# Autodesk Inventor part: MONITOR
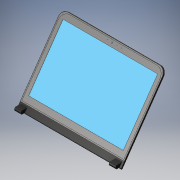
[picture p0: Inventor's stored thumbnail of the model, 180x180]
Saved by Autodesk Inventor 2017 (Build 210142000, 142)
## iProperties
Created: 2017-02
Part Number: MONITOR
Material: Generic
Document SubType Name: Modeling
Designer: Ali
Density: 1 g/cm^3
Appearance: Default
Author: Ali
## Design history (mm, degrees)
sketch "Sketch1"
  geometry: L1 (-145, 250)-(145, 250); L2 (165, 230)-(165, 0); L3 (165, 0)-(-165, 0); L4 (-165, 0)-(-165, 230); A1 r 20 centre (-145, 230) between (-145, 250) and (-165, 230); A2 r 20 centre (145, 230) between (165, 230) and (145, 250); 2 further points
  constraints: 8 end point, 4 point on circle, 4 tangent, 2 centre point, 2 parallel, 2 point on line, 1 equal radius, 1 horizontal, 1 perpendicular
  dimensions: "d2" = 330 distance of L2.end L3.end; "d3" = 250 distance of point (165, 250) L2.end; "d4" = 20 radius of A1 (derived)
extrude "MONITOR" new body sketch "Sketch1" distance "d5" = 5; taper "d6" = 0 deg
sketch "Sketch2"
  geometry: L1 (150, 40)-(-150, 40); L2 (-150, 40)-(-150, 230); L3 (-150, 230)-(150, 230); L4 (150, 230)-(150, 40)
  constraints: 8 end point, 2 parallel, 1 horizontal, 1 perpendicular
  dimensions: "d9" = 300 distance of L2.end L3.end; "d10" = 190 distance of L1.end L2.end
extrude "SCREEN" cut sketch "Sketch2" distance "d11" = 0.5; taper "d12" = 0 deg
sketch "Sketch3"
  geometry: C1 r 2.5 at (0, 240); 1 further point
  constraints: 1 centre point
extrude "CAMERA" join sketch "Sketch3" distance "d14" = 0.25; taper "d15" = 0 deg
sketch "Sketch4"
  geometry: 2 further points
hole "CAMERA" sketch "Sketch4" at (0, 0) diameter "d16" = 1; stored, may be unused: countersink angle "d20" = 90 deg, drill point angle "d22" = 118 deg; dims "d17" = 7.5, "d18" = 3.75, "d19" = 2.5, "d21" = 0.1
sketch "Sketch5"
  geometry: 4 further points
hole "AESTHETICS" sketch "Sketch5" at (15, 240), (30, 240), (-15, 240) diameter "d23" = 1; stored, may be unused: countersink angle "d27" = 90 deg, drill point angle "d29" = 118 deg; dims "d24" = 7.5, "d25" = 3.75, "d26" = 2.5, "d28" = 0.1
sketch "Sketch6"
  geometry: L1 (164.5, 20)-(-164.5, 20); L2 (-164.5, 20)-(-164.5, 229); L3 (-144, 249.5)-(144, 249.5); L4 (164.5, 229)-(164.5, 20); A1 r 20.5 centre (-144, 229) between (-144, 249.5) and (-164.5, 229); A2 r 20.5 centre (144, 229) between (164.5, 229) and (144, 249.5); 2 further points
  constraints: 8 end point, 4 point on circle, 4 point on line, 4 tangent, 2 centre point, 2 parallel, 1 equal radius, 1 horizontal, 1 perpendicular
  dimensions: "d36" = 229.5 distance of L1.end point (-164.5, 249.5); "d37" = 20.5 radius of A1 (derived); "d38" = 329 distance of L1.start L1.end
extrude "SIDE BAND" join sketch "Sketch6" distance "d39" = 0.15; taper "d40" = 0 deg
sketch "Sketch7"
  geometry: L1 (161.5, 23)-(-161.5, 23); L2 (-161.5, 23)-(-161.5, 223); L3 (-138, 246.5)-(138, 246.5); L4 (161.5, 223)-(161.5, 23); A1 r 23.5 centre (-138, 223) between (-138, 246.5) and (-161.5, 223); A2 r 23.5 centre (138, 223) between (161.5, 223) and (138, 246.5); 2 further points
  constraints: 8 end point, 4 point on circle, 4 point on line, 4 tangent, 2 centre point, 2 parallel, 1 equal radius, 1 horizontal, 1 perpendicular
  dimensions: "d47" = 323 distance of point (-161.5, 246.5) point (161.5, 246.5); "d48" = 223.5 distance of L1.end point (-161.5, 246.5); "d49" = 23.5 radius of A1 (derived)
extrude "SIDE BAND 1" cut sketch "Sketch7" distance "d50" = 0.15; taper "d51" = 0 deg
sketch "Sketch8"
  geometry: L1 (0, 0)-(-5, 0); L2 (-5, 0)-(-5, 2.251); L3 (-5, 2.251)-(0, 2.251); L4 (0, 2.251)-(0, 0)
  constraints: 8 end point, 2 parallel, 1 horizontal, 1 perpendicular
extrude "CUT" cut sketch "Sketch8" distance "d52" = 330; taper "d53" = 0 deg
sketch "Sketch9"
  geometry: L1 (0, -227.749)-(5, -227.749); A1 r 2.5 centre (2.5, -227.749) between (0, -227.749) and (5, -227.749)
  constraints: 2 end point, 2 point on circle, 1 centre point
extrude "ROUND BASE" join sketch "Sketch9" distance "d54" = 330; taper "d55" = 0 deg
workplane "Work Plane1"
sketch "Sketch10"
  geometry: L1 (2.296, 5)-(-2.292, 11.553); L2 (2.296, 5)-(10.296, 5); L3 (2.296, 5)-(16.296, 5); L4 (16.296, 5)-(7.102, 18.131); A1 r 5.734 centre (2.405, 14.842) between (7.102, 18.131) and (-2.292, 11.553)
  constraints: 8 end point, 2 point on circle, 1 centre point, 1 equal length, 1 horizontal
  dimensions: "d58" = 8 distance of L1.end L1.start; "d60" = 14 distance of L1.start L3.end; "d62" = 16.03007 distance of L3.end L4.end; "d63" = 5.73406 radius of A1
extrude "HINGE" join sketch "Sketch10" stored distance "d64" = 20; taper "d65" = 0 deg
pattern_linear "HINGE 1" dims "d68" = 300
feature "Move Body1"
feature "Move Body2"
body "Solid1"
other parameters: "d69" = -35 deg, "d71" = 0, "d72" = 0
